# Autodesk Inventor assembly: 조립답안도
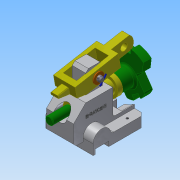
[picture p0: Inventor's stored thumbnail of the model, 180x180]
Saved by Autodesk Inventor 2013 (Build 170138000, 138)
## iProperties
Created: 2016-11
Part Number: 조립답안도
Document SubType Name: Assembly
Designer: Administrator
Author: Administrator
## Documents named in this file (8)
- C:\Users\Administrator\Desktop\461108V1034\조립답안도.iam
- C:\Users\Administrator\Desktop\461108V1034\본체.ipt
- C:\Users\Administrator\Desktop\461108V1034\부시.ipt
- C:\Users\Administrator\Desktop\461108V1034\분할대.ipt
- C:\Users\Administrator\Desktop\461108V1034\분할축.ipt
- C:\Users\Administrator\Desktop\461108V1034\와셔.ipt
- C:\Users\Administrator\Desktop\461108V1034\원통형핀.ipt
- C:\Users\Administrator\Desktop\461108V1034\클레비스핀.ipt
